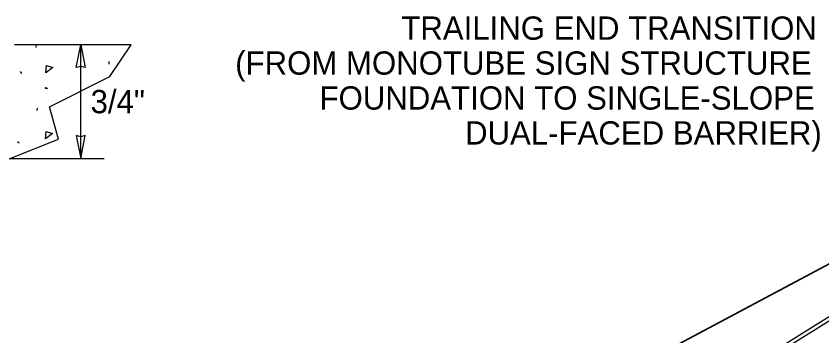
# Model space of a CAD drawing. Extents: x 99862 to 103151, y 100000 to 102076.
# Drawn here: x 102031 to 102585, y 100775 to 100995 of the extents above; entities that cross this region are included whole.
import ezdxf

# ---------------------------------------------------------------- set-up
doc = ezdxf.new("R2010")
doc.units = 0
for name, color, linetype in [('Level 13', 7, 'Continuous'), ('Level 15', 7, 'Continuous'), ('Level 2', 7, 'Continuous'), ('Level 20', 7, 'Continuous'), ('Level 3', 7, 'Continuous')]:
    doc.layers.add(name, color=color, linetype=linetype)

msp = doc.modelspace()

# ---------------------------------------------------------------- linework, layer by layer
at = {"layer": 'Level 13'}
for p, q in [((102110.33, 100975.11), (102030.33, 100975.11)), ((102045.15, 100973.24), (102045.27, 100974.98)), ((102095.72, 100953.27), (102110.33, 100975.11)), ((102095.24, 100961.8), (102095.36, 100963.54)), ((102034.27, 100956.78), (102034.98, 100955.34)), ((102054.28, 100932.51), (102095.72, 100953.27)), ((102051.18, 100945.76), (102052.21, 100945)), ((102051.98, 100945.62), (102053.02, 100944.86)), ((102060.43, 100910.21), (102054.28, 100932.51)), ((102045.83, 100929.8), (102045.95, 100931.55)), ((102005.95, 100888.6), (102060.43, 100910.21)), ((102032.43, 100908.48), (102033.46, 100907.72))]:
    msp.add_line(p, q, dxfattribs=at)
for points in [[(102051.86, 100955.84), (102052.34, 100960.74), (102056.59, 100959.45), (102051.86, 100955.84)], [(102051.53, 100910.52), (102052.01, 100915.42), (102056.26, 100914.13), (102051.53, 100910.52)]]:
    msp.add_lwpolyline(points, dxfattribs=at)
at = {"layer": 'Level 15'}
for p, q in [((102075.76, 100896.9), (102075.76, 100975.11)), ((101965.56, 100896.9), (102091.76, 100896.9))]:
    msp.add_line(p, q, dxfattribs=at)
for points in [[(102075.77, 100975.11), (102078.85, 100959.39), (102075.77, 100960.11), (102072.68, 100959.39)], [(102075.77, 100896.9), (102078.85, 100912.63), (102075.77, 100911.9), (102072.68, 100912.63)]]:
    msp.add_lwpolyline(points, close=True, dxfattribs=at)
at = {"layer": 'Level 2'}
for p, q in [((102110.33, 100975.11), (102030.33, 100975.11)), ((102653.25, 100858.7), (102444.48, 100747.35)), ((102445.74, 100747.82), (102654.51, 100859.17))]:
    msp.add_line(p, q, dxfattribs=at)
at = {"layer": 'Level 3'}
for p, q in [((102679.75, 100844.6), (102486.89, 100724.07)), ((102488.15, 100722.14), (102681.01, 100842.67))]:
    msp.add_line(p, q, dxfattribs=at)

# ---------------------------------------------------------------- texts
at = {"layer": 'Level 20'}
for s, p in [('TRAILING END TRANSITION', (102295.83, 100978.5)), ('(FROM MONOTUBE SIGN STRUCTURE', (102181.79, 100954.5)), ('3/4"', (102082.5, 100928.01)), ('FOUNDATION TO SINGLE-SLOPE', (102239.67, 100930.5)), ('DUAL-FACED BARRIER)', (102339.59, 100906.5))]:
    msp.add_text(s, height=16, dxfattribs=at).set_placement(p)

doc.saveas('drawing.dxf')
